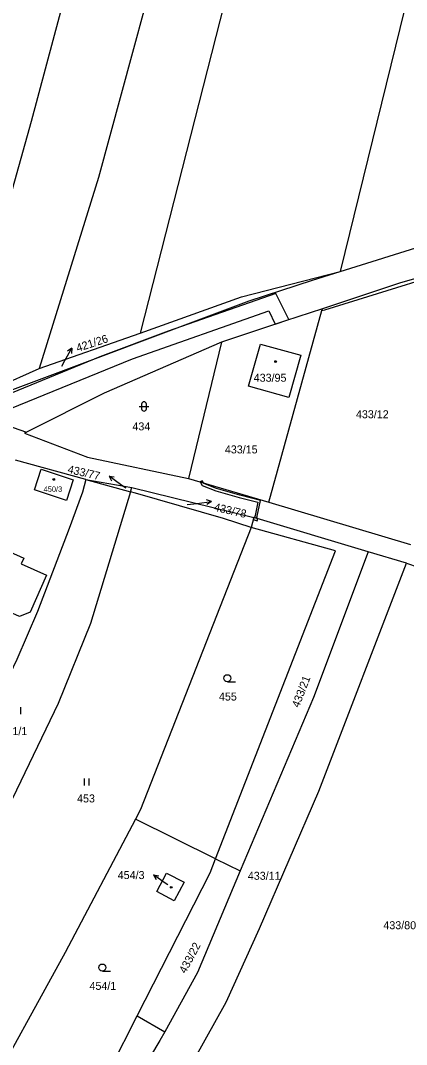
# Model space of a CAD drawing. Extents: x -757266 to -753360, y -1162585 to -1157740.
# Drawn here: x -754402 to -754320, y -1161564.9 to -1161347.3 of the extents above; entities that cross this region are included whole.
import ezdxf

# ---------------------------------------------------------------- set-up
doc = ezdxf.new("R2010")
doc.units = 0
for name, color, linetype in [('Hranice parcel', 7, 'Continuous'), ('Parcelní čísla', 7, 'Continuous'), ('Pop  PČ popisy', 7, 'Continuous'), ('Věcná břemena k části', 7, 'Continuous'), ('Značky budov', 7, 'Continuous'), ('Značky kultur', 7, 'Continuous')]:
    doc.layers.add(name, color=color, linetype=linetype)

msp = doc.modelspace()

# ---------------------------------------------------------------- linework, layer by layer
at = {"layer": 'Hranice parcel'}
for p, q in [((-754334.08, -1161400.67), (-754315.74, -1161394.89)), ((-754349.2, -1161449.67), (-754337.94, -1161408.93)), ((-754337.94, -1161408.93), (-754337.83, -1161408.54)), ((-754397.98, -1161421.24), (-754376.56, -1161413.76)), ((-754359.26, -1161415.65), (-754366.28, -1161444.6)), ((-754416.72, -1161429.57), (-754397.98, -1161421.24)), ((-754388.08, -1161444.8), (-754403, -1161440.7)), ((-754388.08, -1161444.8), (-754378.31, -1161446.56)), ((-754388.08, -1161444.8), (-754378.58, -1161447.46)), ((-754378.58, -1161447.46), (-754378.31, -1161446.56)), ((-754378.31, -1161446.56), (-754352.41, -1161452.88)), ((-754366.28, -1161444.6), (-754349.2, -1161449.67)), ((-754349.2, -1161449.67), (-754319.14, -1161458.62)), ((-754352.41, -1161452.88), (-754353, -1161455)), ((-754328.1, -1161460.2), (-754352.41, -1161452.88)), ((-754320, -1161462.6), (-754328.1, -1161460.2)), ((-754320, -1161462.6), (-754277.66, -1161477.48)), ((-754393.98, -1161492.43), (-754403.63, -1161512.57)), ((-754360.53, -1161525.4), (-754377.53, -1161516.99)), ((-754360.53, -1161525.4), (-754355.3, -1161527.99)), ((-754394.12, -1161592.08), (-754377.15, -1161558.76)), ((-754377.15, -1161558.76), (-754371.33, -1161562.19))]:
    msp.add_line(p, q, dxfattribs=at)
for points in [[(-754240.23, -1160869.33), (-754258.1, -1160934.43), (-754274.18, -1161002.2), (-754288.17, -1161067.13), (-754298.61, -1161110.97), (-754317.3, -1161179.08), (-754343.58, -1161284.28), (-754376.56, -1161413.76)], [(-754261.38, -1160876.02), (-754273.65, -1160920.93), (-754281.63, -1160958.76), (-754310.59, -1161082.5), (-754337.36, -1161190.1), (-754364.7, -1161299.26), (-754368.3, -1161317.87), (-754385.39, -1161380.66), (-754397.98, -1161421.24)], [(-754283.62, -1160882.92), (-754298.95, -1160954.38), (-754325.71, -1161070.45), (-754355.11, -1161191.34), (-754367.94, -1161239.65), (-754384.51, -1161312.03), (-754399.66, -1161368.8), (-754416.72, -1161429.57)], [(-754249.41, -1161060.34), (-754251.78, -1161070.56), (-754266.17, -1161126.61), (-754288.27, -1161212.11), (-754304.75, -1161281.16), (-754334.08, -1161400.67)], [(-754337.94, -1161408.93), (-754337.33, -1161408.75), (-754301.76, -1161397.72)], [(-754301.69, -1161397.45), (-754321.25, -1161403.06), (-754337.83, -1161408.54)], [(-754426.28, -1161433.52), (-754405.83, -1161426.55), (-754353.37, -1161406.89), (-754339.92, -1161402.51), (-754334.08, -1161400.67)], [(-754376.56, -1161413.76), (-754355.02, -1161406.02), (-754334.08, -1161400.67)], [(-754337.83, -1161408.54), (-754345.71, -1161411.09), (-754359.26, -1161415.65)], [(-754359.26, -1161415.65), (-754384.2, -1161426.5), (-754400.65, -1161434.77)], [(-754344.96, -1161427.43), (-754353.51, -1161424.99), (-754351.01, -1161416.05), (-754342.43, -1161418.41), (-754344.96, -1161427.43)], [(-754413.16, -1161437.75), (-754404.95, -1161433.28), (-754400.65, -1161434.77)], [(-754400.65, -1161434.77), (-754401.1, -1161435), (-754387.75, -1161440.1), (-754366.28, -1161444.6)], [(-754397.53, -1161442.65), (-754390.76, -1161444.89), (-754392.15, -1161449.27), (-754398.95, -1161447.01), (-754397.53, -1161442.65)], [(-754388.08, -1161444.8), (-754388.81, -1161447.55), (-754391.61, -1161455.26), (-754398.33, -1161472.84), (-754402.73, -1161483.07), (-754405.69, -1161489.32), (-754407.33, -1161492.84), (-754414.99, -1161507.42), (-754421.68, -1161519.1)], [(-754378.58, -1161447.46), (-754387.07, -1161475.43), (-754393.98, -1161492.43)], [(-754353, -1161455), (-754358.83, -1161453.09), (-754377.55, -1161447.75), (-754378.58, -1161447.46)], [(-754353, -1161455), (-754376.45, -1161514.95), (-754377.53, -1161516.99)], [(-754360.53, -1161525.4), (-754335.05, -1161460), (-754353, -1161455)], [(-754411.51, -1161469.92), (-754409.25, -1161464.76), (-754408.95, -1161464.86), (-754406.46, -1161459.22), (-754401.25, -1161461.53), (-754401.78, -1161462.74), (-754396.4, -1161465.13), (-754399.9, -1161473.02), (-754402.17, -1161473.91), (-754404.35, -1161472.98), (-754404.65, -1161472.15), (-754405.76, -1161471.68), (-754406.98, -1161474.57), (-754412.19, -1161472.24), (-754411.24, -1161470.08), (-754411.51, -1161469.92)], [(-754328.1, -1161460.2), (-754339.75, -1161491.15), (-754355.3, -1161527.99)], [(-754383, -1161598.65), (-754374.1, -1161584.2), (-754358.25, -1161555.85), (-754351.2, -1161540.25), (-754338.6, -1161511.05), (-754320, -1161462.6)], [(-754377.53, -1161516.99), (-754392.45, -1161545.35), (-754410.6, -1161578.2)], [(-754377.15, -1161558.76), (-754361.69, -1161528.39), (-754360.53, -1161525.4)], [(-754367.22, -1161530.36), (-754369.33, -1161534.34), (-754373.01, -1161532.35), (-754370.92, -1161528.47), (-754367.22, -1161530.36)], [(-754355.3, -1161527.99), (-754364.4, -1161549.55), (-754371.33, -1161562.19)], [(-754371.33, -1161562.19), (-754372.35, -1161564.05), (-754390.4, -1161594.35)]]:
    msp.add_lwpolyline(points, dxfattribs=at)
at = {"layer": 'Pop  PČ popisy'}
for p, q in [((-754392.52, -1161419.57), (-754391.065, -1161416.945)), ((-754391.065, -1161416.945), (-754391.989, -1161417.578)), ((-754391.065, -1161416.945), (-754391.113, -1161418.064)), ((-754393.17, -1161420.76), (-754392.52, -1161419.57)), ((-754380.72, -1161445.87), (-754383.148, -1161444.106)), ((-754383.148, -1161444.106), (-754382.043, -1161444.29)), ((-754383.148, -1161444.106), (-754382.632, -1161445.1)), ((-754379.58, -1161446.7), (-754380.72, -1161445.87)), ((-754366.59, -1161450.17), (-754364.41, -1161449.9)), ((-754364.41, -1161449.9), (-754361.431, -1161449.534)), ((-754361.431, -1161449.534), (-754362.486, -1161449.159)), ((-754361.431, -1161449.534), (-754362.364, -1161450.153)), ((-754371.24, -1161530.57), (-754373.698, -1161528.849)), ((-754373.698, -1161528.849), (-754372.591, -1161529.013)), ((-754373.698, -1161528.849), (-754373.165, -1161529.833)), ((-754370.68, -1161530.96), (-754371.24, -1161530.57))]:
    msp.add_line(p, q, dxfattribs=at)
at = {"layer": 'Věcná břemena k části'}
for points in [[(-754546.67, -1161461.99), (-754542.48, -1161463.44), (-754535.63, -1161463.86), (-754492.58, -1161454.72), (-754440.85, -1161442.86), (-754430.58, -1161439.96), (-754404.2, -1161429.81), (-754378.15, -1161419.18), (-754349.25, -1161409.02), (-754347.87, -1161411.82), (-754345, -1161410.86), (-754347.73, -1161405.3), (-754370.62, -1161413.35), (-754385.13, -1161418.79), (-754405.3, -1161427.03), (-754431.52, -1161437.12), (-754441.59, -1161439.96), (-754493.22, -1161451.8), (-754535.85, -1161460.84), (-754541.88, -1161460.48), (-754545.14, -1161459.35), (-754546.9, -1161459.49)], [(-754363.8, -1161445.34), (-754363.11, -1161445.54), (-754363.36, -1161445.09)], [(-754363.37, -1161446.1), (-754360.51, -1161447.22), (-754355.49, -1161448.65), (-754351.56, -1161449.66), (-754352.16, -1161452.47), (-754352.3, -1161452.91), (-754351.82, -1161453.06), (-754351.68, -1161452.59), (-754350.96, -1161449.3), (-754355.35, -1161448.17), (-754360.35, -1161446.74), (-754363.03, -1161445.7), (-754363.11, -1161445.54), (-754363.8, -1161445.34)], [(-754351.82, -1161453.06), (-754352.3, -1161452.91), (-754352.41, -1161452.88), (-754352.54, -1161453.36), (-754351.72, -1161453.61), (-754351.58, -1161453.13)]]:
    msp.add_lwpolyline(points, close=True, dxfattribs=at)
at = {"layer": 'Značky budov'}
for centre in [(-754347.7968, -1161419.7692), (-754394.8768, -1161444.8192), (-754369.9468, -1161531.4892)]:
    msp.add_circle(centre, 0.175, dxfattribs=at)
at = {"layer": 'Značky kultur'}
for p, q in [((-754376.231, -1161428.811), (-754376.231, -1161429.812)), ((-754375.229, -1161429.812), (-754375.229, -1161428.811)), ((-754376.731, -1161429.311), (-754374.729, -1161429.311)), ((-754358.033, -1161487.8), (-754356.283, -1161487.8)), ((-754401.9, -1161494.68), (-754401.9, -1161493.18)), ((-754388.361, -1161509.87), (-754388.361, -1161508.37)), ((-754387.36, -1161509.87), (-754387.36, -1161508.37)), ((-754384.573, -1161549.27), (-754382.823, -1161549.27))]:
    msp.add_line(p, q, dxfattribs=at)
for centre in [(-754358.0329, -1161487.0498), (-754384.5729, -1161548.5198)]:
    msp.add_circle(centre, 0.75, dxfattribs=at)
for centre, start, end in [((-754375.73, -1161428.8109), 0, 180), ((-754375.73, -1161429.8109), 180, 359.987886)]:
    msp.add_arc(centre, 0.5, start, end, dxfattribs=at)

# ---------------------------------------------------------------- texts
at = {"layer": 'Parcelní čísla'}
for s, rotation, p in [('421/26', 18, (-754389.807, -1161417.748)), ('433/77', 347, (-754392.054, -1161443.402)), ('433/78', 347, (-754360.98, -1161451.445)), ('433/21', 68.999997, (-754342.831, -1161493.42)), ('433/22', 62, (-754366.902, -1161549.904))]:
    msp.add_text(s, height=1.7, rotation=rotation, dxfattribs=at).set_placement(p)
for s, height, p in [('433/95', 1.7, (-754352.437, -1161424.06)), ('433/12', 1.7, (-754330.73, -1161431.82)), ('434', 1.7, (-754378.19, -1161434.4)), ('433/15', 1.7, (-754358.56, -1161439.29)), ('450/3', 1.139, (-754397.04, -1161447.449)), ('455', 1.7, (-754359.82, -1161491.79)), ('451/1', 1.7, (-754406.198, -1161499.14)), ('453', 1.7, (-754389.94, -1161513.44)), ('454/3', 1.7, (-754381.307, -1161529.72)), ('433/11', 1.7, (-754353.69, -1161529.87)), ('433/80', 1.7, (-754324.91, -1161540.38)), ('454/1', 1.7, (-754387.3, -1161553.26))]:
    msp.add_text(s, height=height, dxfattribs=at).set_placement(p)

doc.saveas('drawing.dxf')
